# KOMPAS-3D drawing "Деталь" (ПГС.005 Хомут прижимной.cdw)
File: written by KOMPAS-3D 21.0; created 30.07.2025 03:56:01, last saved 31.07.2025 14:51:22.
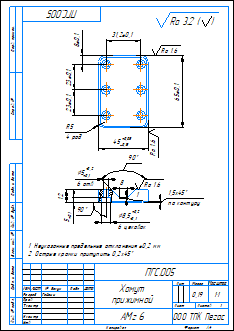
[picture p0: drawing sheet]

Sheet 1: A4, portrait

Document properties: Автор: rinat.gaysin.00@bk.ru; Полное имя файла: C:\Users\User\Desktop\ПЕРСПЕКТИВА кд\Чертежи\ПГС.005 Хомут прижимной.cdw; Знак неуказанной шероховатости: 4; Параметр неуказанной шероховатости: Ra 3.2; Масса: 0.19206

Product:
- Part/product: Деталь
    Масса: 0.19206

Title block, sheet 1: Наименование: Хомут / прижимной; designation: ПГС.005; Материал: АМг 6; Масса: 0,19; Количество листов документа: 1; organisation: ООО ТПК Пегас; Форматы листов документа: A4; stored path: C:\Users\User\Desktop\ПЕРСПЕКТИВА кд\Чертежи\Хомут зажимной.cdw; Разработал: Гайсин

Views: Вид 1, Спереди, Проекционный вид 3, Местный разрез 1
Referenced files in C:\Users\rinat\OneDrive\Рабочий стол\ПЕРСПЕКТИВА кд\Модель\: Хомут зажимной.m3d
Referenced files in C:\Users\User\Desktop\ПЕРСПЕКТИВА кд\Модель\: ПГС.005 Хомут прижимной.m3d
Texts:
  Ra 1.6
  по контуру
  Ra 3.2
  Ra 3.2 ( )
Dimensions and other numbers on the sheet: 31,2±0,1; 23±0,1; 8±0,1; 65±0,1; 45; 5; 4 рад; 7; 1; 1,5; 12; 8,5; 6 цековок; 6 отв; 1:1; 0,19

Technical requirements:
  Неуказанные предельные отклонения  0,2 мм
  Острые кромки притупить 0,2х45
